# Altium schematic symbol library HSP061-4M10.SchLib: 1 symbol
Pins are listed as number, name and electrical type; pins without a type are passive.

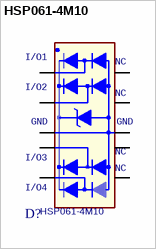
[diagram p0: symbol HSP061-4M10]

## HSP061-4M10
designator D?
footprint ST_QFN50P260X110X50-10L
pins: 1 I/O1, 2 I/O2, 3 GND, 4 I/O3, 5 I/O4, 6 NC1, 7 NC2, 8 GND1, 9 NC3, 10 NC4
